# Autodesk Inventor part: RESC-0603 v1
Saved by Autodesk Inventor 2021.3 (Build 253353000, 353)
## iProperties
Created: 2023-09
Part Number: RESC-0603 v1
Material: Generic
Document SubType Name: Modeling
Designer: AdminForWorker
Density: 1 g/cm^3
Appearance: Default
Title: RESC-0603 v1
Author: AdminForWorker
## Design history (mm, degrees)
feature "Body1"
feature "Body2"
feature "Body3"
body "Solid1"
body "Solid2"
body "Solid3"
